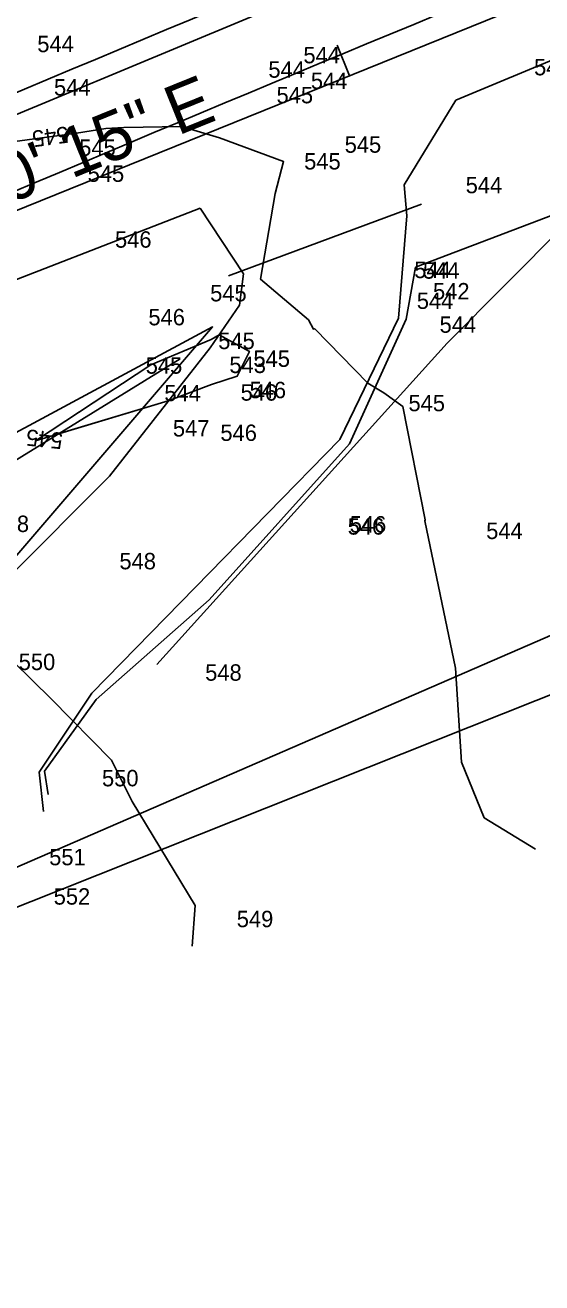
# Model space of a CAD drawing. Extents: x 1787461 to 1970323, y 938412 to 1118748.
# Drawn here: x 1967286.2 to 1967349.3, y 1117535 to 1117688.4 of the extents above; entities that cross this region are included whole.
import ezdxf

# ---------------------------------------------------------------- set-up
doc = ezdxf.new("R2010")
doc.units = 0
for name, color, linetype in [('Default', 7, 'Continuous'), ('HHA ADDITIONAL XSs', 7, 'Continuous'), ('Level 1', 7, 'Continuous'), ('RD_EX_DR_Pipe', 7, 'Continuous'), ('RD_EX_Driveway', 7, 'Continuous'), ('RD_EX_DV_Prop', 7, 'Continuous'), ('RD_EX_Fence_Other', 7, 'Continuous'), ('RD_EX_Road', 7, 'Continuous'), ('RD_EX_VEG', 7, 'Continuous'), ('RD_HC_CL', 7, 'Continuous'), ('RD_HC_CL_Rel', 7, 'Continuous'), ('RD_HC_Data', 7, 'Continuous'), ('RD_HC_Data_Tic', 7, 'Continuous'), ('RD_PD_Final_TrvlWay', 7, 'Continuous')]:
    doc.layers.add(name, color=color, linetype=linetype)

msp = doc.modelspace()

# ---------------------------------------------------------------- linework, layer by layer
at = {"layer": 'Default'}
for points in [[(1967270.77, 1117672.26), (1967292.51, 1117675.18), (1967296.1, 1117675.77), (1967298.27, 1117675.87), (1967305.32, 1117676.01), (1967309.95, 1117674.6), (1967317.78, 1117671.72), (1967316.78, 1117667.82), (1967314.97, 1117657.37), (1967320.85, 1117652.41), (1967321.44, 1117651.29), (1967321.59, 1117651.34), (1967328.09, 1117644.69), (1967330.04, 1117643.52), (1967332.35, 1117641.85), (1967335.08, 1117628.04), (1967335.06, 1117627.92), (1967338.77, 1117609.95), (1967339.53, 1117598.47), (1967342.29, 1117591.68), (1967348.55, 1117587.86)], [(1967291.92, 1117675.1), (1967292.51, 1117675.18), (1967296.1, 1117675.77), (1967298.27, 1117675.87), (1967305.32, 1117676.01), (1967309.95, 1117674.6), (1967317.78, 1117671.72), (1967316.78, 1117667.82), (1967314.97, 1117657.37), (1967320.85, 1117652.41), (1967321.44, 1117651.29), (1967321.59, 1117651.34), (1967328.09, 1117644.69), (1967330.04, 1117643.52), (1967332.35, 1117641.85), (1967335.08, 1117628.04), (1967335.06, 1117627.92), (1967338.77, 1117609.95), (1967339.53, 1117598.47), (1967342.29, 1117591.68), (1967348.55, 1117587.86)], [(1967291.92, 1117675.1), (1967292.51, 1117675.18), (1967296.1, 1117675.77), (1967298.27, 1117675.87), (1967305.32, 1117676.01), (1967309.95, 1117674.6), (1967317.78, 1117671.72), (1967316.78, 1117667.82), (1967314.97, 1117657.37), (1967320.85, 1117652.41), (1967321.44, 1117651.29), (1967321.59, 1117651.34), (1967328.09, 1117644.69), (1967330.04, 1117643.52), (1967332.35, 1117641.85), (1967335.08, 1117628.04), (1967335.06, 1117627.92), (1967338.77, 1117609.95), (1967339.53, 1117598.47), (1967342.29, 1117591.68), (1967348.55, 1117587.86)], [(1967291.92, 1117675.1), (1967292.51, 1117675.18), (1967296.1, 1117675.77), (1967298.27, 1117675.87), (1967305.32, 1117676.01), (1967309.95, 1117674.6), (1967317.78, 1117671.72), (1967316.78, 1117667.82), (1967314.97, 1117657.37), (1967320.85, 1117652.41), (1967321.44, 1117651.29), (1967321.59, 1117651.34), (1967328.09, 1117644.69), (1967330.04, 1117643.52), (1967332.35, 1117641.85), (1967335.08, 1117628.04), (1967335.06, 1117627.92), (1967338.77, 1117609.95), (1967339.53, 1117598.47), (1967342.29, 1117591.68), (1967348.55, 1117587.86)], [(1967291.92, 1117675.1), (1967292.51, 1117675.18), (1967296.1, 1117675.77), (1967298.27, 1117675.87), (1967305.32, 1117676.01), (1967309.95, 1117674.6), (1967317.78, 1117671.72), (1967316.78, 1117667.82), (1967314.97, 1117657.37), (1967320.85, 1117652.41), (1967321.44, 1117651.29), (1967321.59, 1117651.34), (1967328.09, 1117644.69), (1967330.04, 1117643.52), (1967332.35, 1117641.85), (1967335.08, 1117628.04), (1967335.06, 1117627.92), (1967338.77, 1117609.95), (1967339.53, 1117598.47), (1967342.29, 1117591.68), (1967348.55, 1117587.86)], [(1967291.92, 1117675.1), (1967292.51, 1117675.18), (1967296.1, 1117675.77), (1967298.27, 1117675.87), (1967305.32, 1117676.01), (1967309.95, 1117674.6), (1967317.78, 1117671.72), (1967316.78, 1117667.82), (1967314.97, 1117657.37), (1967320.85, 1117652.41), (1967321.44, 1117651.29), (1967321.59, 1117651.34), (1967328.09, 1117644.69), (1967330.04, 1117643.52), (1967332.35, 1117641.85), (1967335.08, 1117628.04), (1967335.06, 1117627.92), (1967338.77, 1117609.95), (1967339.53, 1117598.47), (1967342.29, 1117591.68), (1967348.55, 1117587.86)], [(1967291.92, 1117675.1), (1967292.51, 1117675.18), (1967296.1, 1117675.77), (1967298.27, 1117675.87), (1967305.32, 1117676.01), (1967309.95, 1117674.6), (1967317.78, 1117671.72), (1967316.78, 1117667.82), (1967314.97, 1117657.37), (1967320.85, 1117652.41), (1967321.44, 1117651.29), (1967321.59, 1117651.34), (1967328.09, 1117644.69), (1967330.04, 1117643.52), (1967332.35, 1117641.85), (1967335.08, 1117628.04), (1967335.06, 1117627.92), (1967338.77, 1117609.95), (1967339.53, 1117598.47), (1967342.29, 1117591.68), (1967348.55, 1117587.86)], [(1967309.94, 1117650.58), (1967313.62, 1117648.56), (1967313.62, 1117648.56), (1967313.62, 1117648.56), (1967312.14, 1117645.55), (1967308.98, 1117644.54), (1967303.7, 1117642.54), (1967287.5, 1117637.68), (1967301.58, 1117646.92), (1967308.95, 1117650.01), (1967309.94, 1117650.58)], [(1967289.4, 1117638.93), (1967301.58, 1117646.92), (1967308.95, 1117650.01), (1967309.94, 1117650.58)], [(1967289.4, 1117638.93), (1967301.58, 1117646.92), (1967308.95, 1117650.01), (1967309.94, 1117650.58)], [(1967289.4, 1117638.93), (1967301.58, 1117646.92), (1967308.95, 1117650.01), (1967309.94, 1117650.58)], [(1967289.4, 1117638.93), (1967301.58, 1117646.92), (1967308.95, 1117650.01), (1967309.94, 1117650.58)], [(1967289.4, 1117638.93), (1967301.58, 1117646.92), (1967308.95, 1117650.01), (1967309.94, 1117650.58)], [(1967289.4, 1117638.93), (1967301.58, 1117646.92), (1967308.95, 1117650.01), (1967309.94, 1117650.58)], [(1967309.94, 1117650.58), (1967313.62, 1117648.56), (1967313.62, 1117648.56), (1967313.62, 1117648.56), (1967312.14, 1117645.55), (1967308.98, 1117644.54), (1967303.7, 1117642.54), (1967291.07, 1117638.75)], [(1967309.94, 1117650.58), (1967313.62, 1117648.56), (1967313.62, 1117648.56), (1967313.62, 1117648.56), (1967312.14, 1117645.55), (1967308.98, 1117644.54), (1967303.7, 1117642.54), (1967291.07, 1117638.75)], [(1967309.94, 1117650.58), (1967313.62, 1117648.56), (1967313.62, 1117648.56), (1967313.62, 1117648.56), (1967312.14, 1117645.55), (1967308.98, 1117644.54), (1967303.7, 1117642.54), (1967291.07, 1117638.75)], [(1967309.94, 1117650.58), (1967313.62, 1117648.56), (1967313.62, 1117648.56), (1967313.62, 1117648.56), (1967312.14, 1117645.55), (1967308.98, 1117644.54), (1967303.7, 1117642.54), (1967291.07, 1117638.75)], [(1967309.94, 1117650.58), (1967313.62, 1117648.56), (1967313.62, 1117648.56), (1967313.62, 1117648.56), (1967312.14, 1117645.55), (1967308.98, 1117644.54), (1967303.7, 1117642.54), (1967291.07, 1117638.75)], [(1967309.94, 1117650.58), (1967313.62, 1117648.56), (1967313.62, 1117648.56), (1967313.62, 1117648.56), (1967312.14, 1117645.55), (1967308.98, 1117644.54), (1967303.7, 1117642.54), (1967291.07, 1117638.75)], [(1967161.37, 1117586.18), (1967175.08, 1117591.23), (1967176.56, 1117591.75), (1967183.26, 1117594.21), (1967199.73, 1117599.91), (1967207.48, 1117602.37), (1967219.12, 1117606.34), (1967231.92, 1117610.29), (1967237.86, 1117612.28), (1967253.72, 1117617.02), (1967257.35, 1117616.45), (1967258.74, 1117616.11), (1967284.82, 1117610.72), (1967289.39, 1117606.2), (1967296.77, 1117598.7), (1967299.3, 1117593.67), (1967306.99, 1117580.97), (1967306.62, 1117576.04)], [(1967283.72, 1117610.95), (1967284.82, 1117610.72), (1967289.39, 1117606.2), (1967296.77, 1117598.7), (1967299.3, 1117593.67), (1967306.99, 1117580.97), (1967306.62, 1117576.04)], [(1967283.72, 1117610.95), (1967284.82, 1117610.72), (1967289.39, 1117606.2), (1967296.77, 1117598.7), (1967299.3, 1117593.67), (1967306.99, 1117580.97), (1967306.62, 1117576.04)], [(1967283.72, 1117610.95), (1967284.82, 1117610.72), (1967289.39, 1117606.2), (1967296.77, 1117598.7), (1967299.3, 1117593.67), (1967306.99, 1117580.97), (1967306.62, 1117576.04)], [(1967283.72, 1117610.95), (1967284.82, 1117610.72), (1967289.39, 1117606.2), (1967296.77, 1117598.7), (1967299.3, 1117593.67), (1967306.99, 1117580.97), (1967306.62, 1117576.04)], [(1967283.72, 1117610.95), (1967284.82, 1117610.72), (1967289.39, 1117606.2), (1967296.77, 1117598.7), (1967299.3, 1117593.67), (1967306.99, 1117580.97), (1967306.62, 1117576.04)], [(1967283.72, 1117610.95), (1967284.82, 1117610.72), (1967289.39, 1117606.2), (1967296.77, 1117598.7), (1967299.3, 1117593.67), (1967306.99, 1117580.97), (1967306.62, 1117576.04)]]:
    msp.add_lwpolyline(points, dxfattribs=at)
at = {"layer": 'HHA ADDITIONAL XSs'}
msp.add_lwpolyline([(1969308.89, 1117819.66), (1967912.94, 1117853.44), (1967442.55, 1117653.93), (1967107.32, 1117508.48)], dxfattribs=at)
at = {"layer": 'Level 1'}
msp.add_lwpolyline([(1968654.57, 1117840.68), (1968058.24, 1117848.48), (1967686.38, 1117740.3), (1966964.76, 1117453.35)], dxfattribs=at)
at = {"layer": 'RD_EX_DR_Pipe'}
msp.add_line((1967311.05, 1117657.77), (1967334.63, 1117666.54), dxfattribs=at)
at = {"layer": 'RD_EX_Driveway'}
for points in [[(1967288.48, 1117592.45), (1967287.93, 1117597.25), (1967294.39, 1117606.88), (1967306.98, 1117619.76), (1967324.64, 1117637.84), (1967331.81, 1117652.63), (1967332.84, 1117665.11), (1967332.53, 1117668.87), (1967338.81, 1117679.22)], [(1967307.6, 1117666.03), (1967312.88, 1117658.05), (1967312.4, 1117654.22), (1967308.84, 1117649.01), (1967296.51, 1117633.35), (1967284.22, 1117621.05), (1967276.43, 1117608.93), (1967274.02, 1117593.22)]]:
    msp.add_lwpolyline(points, dxfattribs=at)
at = {"layer": 'RD_EX_DV_Prop'}
msp.add_line((1966769.51, 1117457.48), (1967696.84, 1117832.06), dxfattribs=at)
at = {"layer": 'RD_EX_Fence_Other'}
for points in [[(1967289.05, 1117594.53), (1967288.6, 1117597.38), (1967294.91, 1117606.13), (1967308.72, 1117618.25), (1967325.85, 1117637.29), (1967332.75, 1117652.49), (1967333.91, 1117658.84), (1967392.48, 1117681.09)], [(1967260.47, 1117628.39), (1967281.3, 1117636.63), (1967309.11, 1117651.56), (1967274.94, 1117611.82), (1967271.94, 1117593.66)]]:
    msp.add_lwpolyline(points, dxfattribs=at)
at = {"layer": 'RD_EX_Road'}
for points in [[(1966768.28, 1117466.83), (1966868.93, 1117506.7), (1966969.96, 1117548.31), (1967069.86, 1117589.6), (1967171.37, 1117630.89), (1967269.56, 1117671.02), (1967319.89, 1117691.93), (1967370.29, 1117712.23), (1967469.03, 1117750.91), (1967565.44, 1117788.86), (1967660.02, 1117826.88), (1967693.17, 1117840.55), (1967696.66, 1117832.16)], [(1967338.81, 1117679.22), (1967378.03, 1117695.56), (1967474.86, 1117733.75), (1967572.69, 1117772.86), (1967666.47, 1117810.1), (1967700.41, 1117823.36), (1967696.66, 1117832.16)], [(1966774.52, 1117449.93), (1966874.96, 1117489.75), (1966977.23, 1117531.51), (1967077.03, 1117572.42), (1967179.47, 1117614.42), (1967276.75, 1117654.08), (1967307.6, 1117666.03)]]:
    msp.add_lwpolyline(points, dxfattribs=at)
at = {"layer": 'RD_EX_VEG'}
for points in [[(1967302.31, 1117610.37), (1967337.76, 1117649.58), (1967352.05, 1117663.92), (1967393.53, 1117676.59), (1967483.38, 1117717.02), (1967710.35, 1117806.03), (1967888.86, 1117873.57), (1967928.06, 1117882.04), (1967957.92, 1117887.35), (1967975.7, 1117893.86), (1968013.09, 1117903.71), (1968102.91, 1117899.22), (1968154.08, 1117904.84), (1968208.62, 1117905.24), (1968319.32, 1117902.87), (1968421.81, 1117901.58), (1968527.92, 1117886.31)], [(1966832.92, 1117460.39), (1966879.09, 1117474.94), (1966985, 1117515.6), (1967082.35, 1117552.01), (1967187.28, 1117596.9), (1967283.89, 1117634.57), (1967305.16, 1117647.66)]]:
    msp.add_lwpolyline(points, dxfattribs=at)
at = {"layer": 'RD_HC_CL'}
msp.add_line((1966769.51, 1117457.48), (1967848.24, 1117893.22), dxfattribs=at)
at = {"layer": 'RD_HC_CL_Rel'}
msp.add_arc((1969513.16, 1112401.48), 5729.58, 111.995838, 114.000153, dxfattribs=at)
at = {"layer": 'RD_HC_Data_Tic'}
msp.add_line((1967325.84, 1117682.2), (1967324.34, 1117685.91), dxfattribs=at)
at = {"layer": 'RD_PD_Final_TrvlWay'}
for radius, start, end in [(5740.58, 111.995838, 114.000153), (5718.58, 111.99584, 114.00015)]:
    msp.add_arc((1969513.16, 1112401.48), radius, start, end, dxfattribs=at)

# ---------------------------------------------------------------- texts
at = {"layer": 'Default'}
for s, p in [('544', (1967287.71, 1117685.07)), ('544', (1967320.21, 1117683.71)), ('544', (1967348.38, 1117682.24)), ('544', (1967315.93, 1117681.95)), ('544', (1967321.12, 1117680.57)), ('544', (1967289.75, 1117679.78)), ('545', (1967316.93, 1117678.83)), ('545', (1967292.83, 1117672.42)), ('545', (1967325.25, 1117672.8)), ('545', (1967320.3, 1117670.76)), ('545', (1967293.86, 1117669.25)), ('544', (1967340.03, 1117667.86)), ('546', (1967297.2, 1117661.22)), ('544', (1967333.75, 1117657.51)), ('544', (1967334.81, 1117657.44)), ('545', (1967308.82, 1117654.67)), ('542', (1967336.04, 1117654.91)), ('544', (1967334.06, 1117653.75)), ('546', (1967301.28, 1117651.75)), ('544', (1967336.84, 1117650.84)), ('545', (1967309.81, 1117648.85)), ('545', (1967300.95, 1117645.85)), ('543', (1967311.17, 1117645.93)), ('545', (1967314.11, 1117646.69)), ('545', (1967314.11, 1117646.69)), ('545', (1967314.11, 1117646.69)), ('545', (1967314.11, 1117646.69)), ('545', (1967314.1, 1117646.68)), ('544', (1967303.23, 1117642.49)), ('546', (1967312.54, 1117642.56)), ('546', (1967313.63, 1117642.86)), ('545', (1967333.04, 1117641.27)), ('547', (1967304.27, 1117638.19)), ('546', (1967310.07, 1117637.65)), ('548', (1967282.24, 1117626.54)), ('546', (1967325.62, 1117626.22)), ('546', (1967325.87, 1117626.48)), ('544', (1967342.53, 1117625.68)), ('548', (1967297.74, 1117621.99)), ('550', (1967285.44, 1117609.7)), ('548', (1967308.21, 1117608.4)), ('550', (1967295.61, 1117595.52)), ('551', (1967289.16, 1117585.89)), ('552', (1967289.71, 1117581.09)), ('549', (1967312.07, 1117578.34))]:
    msp.add_text(s, height=2, dxfattribs=at).set_placement(p)
for rotation, p in [(187.6405, (1967291.4, 1117676.04)), (187.6405, (1967291.4, 1117676.04)), (187.6405, (1967291.4, 1117676.04)), (187.6405, (1967291.4, 1117676.04)), (187.6405, (1967291.4, 1117676.04)), (187.6405, (1967291.4, 1117676.04)), (174.0751, (1967290.9, 1117638.62)), (174.0751, (1967290.9, 1117638.62)), (174.0751, (1967290.9, 1117638.62)), (174.0751, (1967290.9, 1117638.62)), (174.0751, (1967290.9, 1117638.62)), (174.0751, (1967290.9, 1117638.62))]:
    msp.add_text('545', height=2, rotation=rotation, dxfattribs=at).set_placement(p)
at = {"layer": 'RD_HC_Data'}
msp.add_text('N 68%%d 00\' 15" E', height=6, rotation=21.9958, dxfattribs=at).set_placement((1967259.35, 1117656.47))

doc.saveas('drawing.dxf')
